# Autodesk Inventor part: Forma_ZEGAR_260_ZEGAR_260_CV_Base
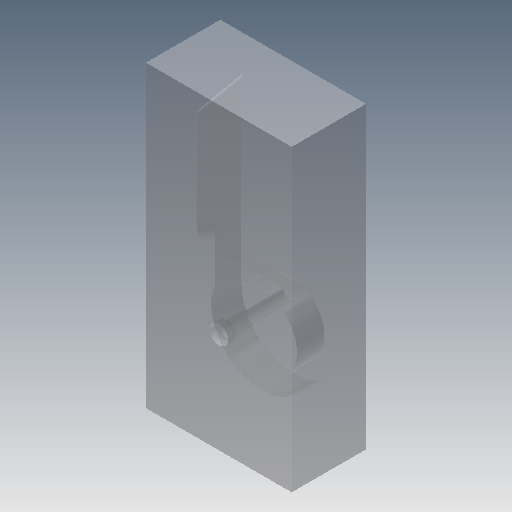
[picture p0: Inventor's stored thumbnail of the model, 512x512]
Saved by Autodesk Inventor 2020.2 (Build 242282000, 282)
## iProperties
Created: 2015-01
Part Number: Forma_ZEGAR_260_ZEGAR_260_CV_Base
Material: Ogólny
Document SubType Name: Modeling
Designer: F.Stasiak
Density: 1 g/cm^3
Appearance: Domyślna
Catalog Web Link: www.expertbooks.pl
Manager: www.cadconsulting.pl
Company: Fabian Stasiak CAD Consulting
Author: F.Stasiak
Subject: Zbiór ćwiczeń. Autodesk Inventor 2020. Kurs Professional
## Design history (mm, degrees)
node "Forma_ZEGAR_260_ZEGAR_260_MP"
sketch "Szkic8"
  geometry: 1 further point
hole "Otwór8" sketch "Szkic8" at (39, -106.407) diameter "d49" = 7; stored, may be unused: countersink angle "d53" = 90 deg, drill point angle "d55" = 118 deg; dims "d50" = 6, "d51" = 10, "d52" = 4, "d54" = 15
feature "Rzeźbienie12"
feature "Bryła14::Forma_ZEGAR_260_ZEGAR_260_MP"
tag "Bryła wyprowadzona5"
node "Bryła5"
feature "Forma_ZEGAR_260_ZEGAR_260_MP_Bodies"
feature "Powierzchnia12"
body "Srf12"
